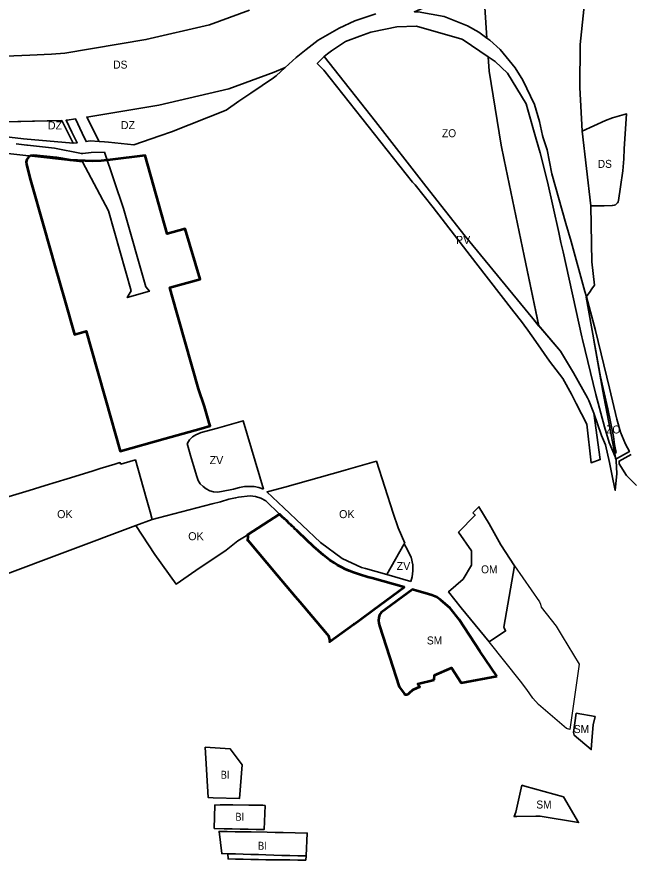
# Model space of a CAD drawing. Extents: x -650276 to -642489, y -1074311 to -1066720.
# Drawn here: x -648741 to -647822, y -1070372 to -1069108 of the extents above; entities that cross this region are included whole.
import ezdxf

# ---------------------------------------------------------------- set-up
doc = ezdxf.new("R2010")
doc.units = 0
doc.header["$LTSCALE"] = 4.8
for name, color, linetype, lineweight in [('12', 7, 'Continuous', 35), ('13', 7, 'Continuous', 35), ('15', 7, 'Continuous', 35), ('18', 7, 'Continuous', 35), ('2', 7, 'Continuous', 35), ('24', 7, 'Continuous', 35), ('25', 7, 'Continuous', 35), ('40', 7, 'Continuous', 35), ('42', 7, 'Continuous', 35), ('60', 7, 'Continuous', 53), ('61', 7, 'Continuous', 25)]:
    doc.layers.add(name, color=color, linetype=linetype, lineweight=lineweight)
doc.layers.add('62', color=7, linetype='Continuous')

msp = doc.modelspace()

# ---------------------------------------------------------------- linework, layer by layer
at = {"layer": '12'}
msp.add_lwpolyline([(-648057.11, -1069851.12), (-648053.61, -1069854.64), (-648078.54, -1069880.01), (-648059.32, -1069908.27), (-648059.5, -1069929.52), (-648071.58, -1069950.39), (-648093.67, -1069969.42), (-648074.96, -1069993.46), (-648032.85, -1070044.73), (-648008.18, -1070028.25), (-648010.44, -1070023.66), (-648010.94, -1070022.65), (-647994.71, -1069930.53), (-648015.11, -1069898.98), (-648032.94, -1069867.46), (-648048.08, -1069841.95)], close=True, dxfattribs=at)
at = {"layer": '13'}
msp.add_lwpolyline([(-648767.83, -1069946.87), (-648562.242, -1069870.301), (-648537.86, -1069861.22), (-648541.06, -1069849.78), (-648546.97, -1069828.68), (-648562.87, -1069771.85), (-648579.63, -1069776.66), (-648584.65, -1069778.1), (-648586.09, -1069775.75), (-648593.59, -1069778.06), (-648615.88, -1069784.93), (-648627.99, -1069788.67), (-648665.05, -1069799.99), (-648698.31, -1069810.16), (-648722.24, -1069817.54), (-648772.48, -1069832.83)], dxfattribs=at)
for points in [[(-648159.1, -1069896.39), (-648169.15, -1069873.81), (-648176.78, -1069851.74), (-648201.83, -1069773.86), (-648247.27, -1069786.64), (-648251.94, -1069787.95), (-648339.05, -1069812.45), (-648363.68, -1069819.31), (-648365.81, -1069819.9), (-648340.38, -1069843.78), (-648285.62, -1069895.71), (-648253.13, -1069919.7), (-648223.99, -1069932.96), (-648218.245, -1069934.595), (-648186.268, -1069943.697), (-648160.04, -1069897.73)], [(-648470.79, -1069843.51), (-648528.11, -1069858.73), (-648537.86, -1069861.22), (-648562.242, -1069870.301), (-648533.79, -1069913.49), (-648502.048, -1069957.969), (-648472.6, -1069937.81), (-648426.82, -1069906.88), (-648409.44, -1069893.25), (-648396.87, -1069885.43), (-648395.03, -1069884.22), (-648347.06, -1069853), (-648367.64, -1069833.35), (-648374.89, -1069829.22), (-648382.8, -1069826.55), (-648391.08, -1069825.45), (-648408.45, -1069827.83), (-648412.74, -1069828.72), (-648422.75, -1069830.78), (-648435.53, -1069834.44), (-648447.98, -1069837.44)]]:
    msp.add_lwpolyline(points, close=True, dxfattribs=at)
at = {"layer": '15'}
for points in [[(-648147.81, -1069355.26), (-648143.81, -1069359.39), (-648116.93, -1069393.25), (-648052.62, -1069476.32), (-647995.61, -1069549.95), (-647984.36, -1069564.49), (-647980.21, -1069569.97), (-647974.74, -1069577.39), (-647962.93, -1069594.39), (-647942.48, -1069623.82), (-647922.32, -1069649.56), (-647909.25, -1069673.35), (-647902.18, -1069687.23), (-647886.43, -1069718.16), (-647879.96, -1069776.1), (-647866.4, -1069771.43), (-647866.4, -1069771.43), (-647875.82, -1069701.85), (-647883.51, -1069682.71), (-647885.665, -1069678.788), (-647906.16, -1069641.48), (-647925.99, -1069608.57), (-647967.53, -1069559.94), (-648068.71, -1069436.57), (-648127.77, -1069361.38), (-648203.01, -1069264.73), (-648280.1, -1069166.97), (-648290.39, -1069177.69), (-648280.46, -1069187.61), (-648147.81, -1069355.26)], [(-648307.13, -1070365.57), (-648319.33, -1070365.32), (-648331.32, -1070364.96), (-648343.31, -1070364.61), (-648355.27, -1070364.25), (-648367.26, -1070363.9), (-648378.49, -1070363.57), (-648389.95, -1070363.23), (-648401.36, -1070362.89), (-648412.88, -1070362.55), (-648424.31, -1070362.21), (-648424.05, -1070370), (-648412.75, -1070370.28), (-648401.35, -1070370.5), (-648390.06, -1070370.72), (-648378.73, -1070370.94), (-648367.67, -1070371.16), (-648355.67, -1070371.28), (-648343.67, -1070371.41), (-648331.67, -1070371.53), (-648319.67, -1070371.65), (-648307.67, -1070371.78)]]:
    msp.add_lwpolyline(points, close=True, dxfattribs=at)
msp.add_lwpolyline([(-648929.112, -1069293.123), (-648642.241, -1069324.949), (-648603.386, -1069398.357), (-648569.22, -1069518.4), (-648575.15, -1069528.35), (-648541.88, -1069518.95), (-648547.3, -1069512.136), (-648581.051, -1069394.771), (-648609.304, -1069310.668), (-648629.16, -1069310.91), (-648641.98, -1069312.45), (-648643.83, -1069312.66), (-648684.39, -1069304.67), (-648724.82, -1069299.92), (-648725.82, -1069299.81), (-648741.58, -1069298.16)], dxfattribs=at)
at = {"layer": '18'}
for points in [[(-648182.01, -1070067.11), (-648197.23, -1070020.37), (-648198.22, -1070016.4), (-648198.48, -1070012.3), (-648198.17, -1070008.05), (-648197.19, -1070003.94), (-648194.84, -1070000.49), (-648147.46, -1069966.19)], [(-648147.46, -1069966.19), (-648140.96, -1069968.01), (-648128.48, -1069971.7)], [(-648128.48, -1069971.7), (-648118.75, -1069974.53), (-648111.44, -1069977.32)], [(-648111.44, -1069977.32), (-648105.79, -1069981.56), (-648091.06, -1069994.07), (-648077.68, -1070011.06), (-648046.83, -1070058.62), (-648021.35, -1070096.14), (-648074.76, -1070106.17)], [(-648152.35, -1070121.05), (-648153.85, -1070122.38), (-648156.07, -1070123.54), (-648159.02, -1070123.71), (-648159.89, -1070122.49), (-648167.48, -1070111.75), (-648182.01, -1070067.11)], [(-648074.76, -1070106.17), (-648089.22, -1070083.27), (-648114.7, -1070094.68), (-648115.11, -1070101.26), (-648139.91, -1070107.48), (-648136.61, -1070111.97)], [(-648136.61, -1070111.97), (-648139.45, -1070112.79), (-648147.02, -1070116.35), (-648152.35, -1070121.05)]]:
    msp.add_lwpolyline(points, dxfattribs=at)
for points in [[(-647902.17, -1070151.64), (-647906.6, -1070180.65), (-647905.17, -1070184.5), (-647879.81, -1070206.08), (-647878.18, -1070186.33), (-647876.74, -1070168.88), (-647873.97, -1070156.58)], [(-647962.82, -1070305.9), (-647956.36, -1070305.77), (-647898.82, -1070315.51), (-647921.51, -1070276.76), (-647979.24, -1070260.71), (-647983.6, -1070259.5), (-647992.71, -1070300.01), (-647995.46, -1070306.55), (-647991.12, -1070306.46)]]:
    msp.add_lwpolyline(points, close=True, dxfattribs=at)
at = {"layer": '2'}
msp.add_lwpolyline([(-648458.28, -1070202.26), (-648454.038, -1070277.767), (-648446.18, -1070278.15), (-648406.8, -1070279.32), (-648403.04, -1070229.15), (-648420.7, -1070204.96)], close=True, dxfattribs=at)
for points in [[(-648368.25, -1070289.71), (-648372.1, -1070289.59), (-648380.97, -1070289.44), (-648392.94, -1070289.25), (-648416.93, -1070288.85), (-648420.39, -1070288.79), (-648428.98, -1070288.92), (-648435.93, -1070288.95), (-648444.15, -1070289.16), (-648444.85, -1070324.47)], [(-648444.85, -1070324.47), (-648444.85, -1070324.47), (-648430.02, -1070324.76), (-648418.1, -1070325), (-648406.09, -1070325.23), (-648394.08, -1070325.47), (-648382.06, -1070325.7), (-648370.07, -1070325.94), (-648368.25, -1070289.71)], [(-648307.13, -1070365.57), (-648305.47, -1070331.23), (-648341.46, -1070330.48), (-648353.32, -1070330.23), (-648365.35, -1070329.98), (-648389.43, -1070329.58), (-648401.41, -1070329.39), (-648413.45, -1070329.19), (-648425.43, -1070329), (-648437.65, -1070328.8), (-648433.46, -1070361.94), (-648424.31, -1070362.21), (-648412.88, -1070362.55)], [(-648412.88, -1070362.55), (-648401.36, -1070362.89), (-648389.95, -1070363.23), (-648378.49, -1070363.57), (-648367.26, -1070363.9), (-648355.27, -1070364.25), (-648343.31, -1070364.61), (-648331.32, -1070364.96), (-648319.33, -1070365.32)]]:
    msp.add_lwpolyline(points, dxfattribs=at)
at = {"layer": '24'}
for points in [[(-648392.002, -1069097.554), (-648451.865, -1069119.456), (-648547.243, -1069141.81), (-648668.959, -1069161.838), (-648688.912, -1069163.603), (-648721.315, -1069164.952), (-648781.015, -1069167.44)], [(-648918.889, -1069268.875), (-648673.267, -1069262.895), (-648656.242, -1069297.116), (-648650.06, -1069296.39), (-648650.58, -1069295.34), (-648658.18, -1069280.27), (-648666.827, -1069262.738), (-648665.007, -1069262.694), (-648665.007, -1069262.694), (-648652.716, -1069260.657), (-648642.74, -1069281.93), (-648636.85, -1069294.49), (-648630.82, -1069293.63), (-648617.434, -1069294.508), (-648635.818, -1069257.857), (-648527.693, -1069239.938), (-648423.173, -1069215.44), (-648354.978, -1069190.492), (-648338.523, -1069183.389), (-648322.14, -1069168.56), (-648306.83, -1069156.57), (-648289.25, -1069142.79), (-648257.5, -1069124.41), (-648234.22, -1069113.6), (-648202.46, -1069103.3)]]:
    msp.add_lwpolyline(points, dxfattribs=at)
msp.add_lwpolyline([(-647860.52, -1069390.72), (-647848.24, -1069390.65), (-647845.25, -1069390.07), (-647843.41, -1069389.23), (-647841.81, -1069387.99), (-647840.42, -1069386.51), (-647839.4, -1069384.73), (-647838.79, -1069382.86), (-647836.2, -1069362.68), (-647832.29, -1069338.58), (-647832.29, -1069338.58), (-647831.19, -1069320.69), (-647830.23, -1069305.38), (-647826.928, -1069253.199), (-647848.17, -1069259.21), (-647858.37, -1069263.03), (-647893.553, -1069279.017), (-647880.326, -1069390.832)], close=True, dxfattribs=at)
at = {"layer": '25'}
msp.add_line((-647862.266, -1069668.613), (-647843.449, -1069768.252), dxfattribs=at)
for points in [[(-647948.18, -1069057.276), (-648039.666, -1069069.279), (-648040.705, -1069069.548), (-648036.291, -1069139.458)], [(-647893.553, -1069279.017), (-647896.67, -1069213.573), (-647896.362, -1069149.171), (-647886.615, -1069053.052)], [(-648036.291, -1069139.458), (-648031.92, -1069142.67), (-648016.36, -1069156.54), (-647993.8, -1069184.11)], [(-648005.47, -1069192.09), (-648024.02, -1069174.7), (-648034.421, -1069167.61)], [(-648034.421, -1069167.61), (-648034.421, -1069167.61), (-648033, -1069189), (-648015, -1069300), (-648010.092, -1069322.087), (-647980.331, -1069465.915), (-647958.34, -1069570.699), (-647925.99, -1069608.57), (-647906.16, -1069641.48), (-647885.665, -1069678.788), (-647885.663, -1069678.794), (-647883.51, -1069682.71), (-647875.82, -1069701.85), (-647875.82, -1069701.85), (-647864.19, -1069735.12), (-647858.44, -1069749.43), (-647852.63, -1069775.7), (-647850.66, -1069785.74), (-647849.165, -1069793.367)], [(-648354.978, -1069190.492), (-648423.173, -1069215.44), (-648527.693, -1069239.938), (-648635.818, -1069257.857)], [(-648526.15, -1069286.21), (-648508.95, -1069280.01), (-648427.08, -1069247.75), (-648407.73, -1069233.88), (-648389.91, -1069221.86), (-648355.81, -1069198.88), (-648351.77, -1069195.88), (-648338.523, -1069183.389), (-648354.978, -1069190.492)], [(-647993.8, -1069184.11), (-647982.58, -1069202.33), (-647965.06, -1069238.95), (-647957.56, -1069264.74), (-647953.01, -1069285.73), (-647951.841, -1069289.09)], [(-647962.2, -1069290.88), (-647974.81, -1069246.86), (-647977.29, -1069238.21), (-648005.47, -1069192.09)], [(-648635.818, -1069257.857), (-648622.995, -1069283.455), (-648617.434, -1069294.508)], [(-647880.326, -1069390.832), (-647880.326, -1069390.832), (-647893.553, -1069279.017)], [(-648617.434, -1069294.508), (-648609.425, -1069295.033), (-648603.228, -1069295.53), (-648565.18, -1069299.46), (-648526.15, -1069286.21)], [(-647852.78, -1069745.71), (-647859.722, -1069722.428), (-647872.87, -1069673.56), (-647892.79, -1069591.06), (-647892.789, -1069591.06), (-647893.75, -1069587.08), (-647922.04, -1069459.71), (-647925.16, -1069445.68), (-647928.41, -1069431.03), (-647945.28, -1069355.1), (-647956.27, -1069311.58), (-647962.2, -1069290.88)], [(-647951.841, -1069289.09), (-647945.63, -1069306.95), (-647938.77, -1069343.17), (-647918.08, -1069417.43), (-647909.67, -1069444.46), (-647889.22, -1069519.32), (-647887.087, -1069527.229), (-647885.782, -1069525.389), (-647882.551, -1069520.835), (-647878.73, -1069515.45)], [(-647878.73, -1069515.45), (-647874.75, -1069509.84), (-647878.93, -1069475.09), (-647880.318, -1069391.297), (-647880.326, -1069390.832)], [(-647843.449, -1069768.252), (-647844.371, -1069761.991), (-647842.438, -1069760.647), (-647845.086, -1069748.753), (-647846.484, -1069736.663), (-647855.158, -1069695.232), (-647865.69, -1069647.32), (-647876.061, -1069592.206), (-647862.266, -1069668.613)], [(-647841.402, -1069792.351), (-647842.489, -1069773.282), (-647842.622, -1069770.956), (-647843.337, -1069769.013), (-647843.443, -1069768.293), (-647852.78, -1069745.71)], [(-647849.165, -1069793.367), (-647843.74, -1069817.63), (-647841.402, -1069792.351)]]:
    msp.add_lwpolyline(points, dxfattribs=at)
msp.add_lwpolyline([(-648730.66, -1069290.43), (-648656.242, -1069297.116), (-648673.267, -1069262.895), (-648761.189, -1069265.035), (-648918.889, -1069268.875), (-648909.86, -1069270.02), (-648861.49, -1069275.34), (-648785.92, -1069284.2), (-648730.66, -1069290.43)], close=True, dxfattribs=at)
msp.add_arc((-648354.978, -1069190.492), 0.000000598, 264.13978, 298.69712, dxfattribs=at)
at = {"layer": '40'}
for points in [[(-648371.21, -1069815.56), (-648401.288, -1069713.154), (-648439.8, -1069724.19), (-648464.45, -1069730.89), (-648472.4, -1069734.1), (-648477.39, -1069737.44), (-648481.79, -1069741.57), (-648485.14, -1069746.55), (-648485.44, -1069747.39), (-648480.267, -1069765.316), (-648476.1, -1069780.3), (-648470.97, -1069796.9), (-648468.82, -1069802.44), (-648465.67, -1069807.49), (-648461.64, -1069811.86), (-648456.88, -1069815.39), (-648451.53, -1069817.98), (-648445.8, -1069819.51), (-648439.89, -1069819.97), (-648433.97, -1069819.3), (-648415.99, -1069815.59), (-648406.84, -1069813.23), (-648399.68, -1069811.88), (-648392.45, -1069811.44), (-648385.21, -1069811.91), (-648378.1, -1069813.29)], [(-648150, -1069954), (-648148, -1069947), (-648147, -1069938), (-648147, -1069929), (-648149.67, -1069917.83), (-648157.81, -1069902.06), (-648160.04, -1069897.73), (-648186.268, -1069943.697)]]:
    msp.add_lwpolyline(points, close=True, dxfattribs=at)
at = {"layer": '42'}
for points in [[(-648100.37, -1069107.1), (-648065.16, -1069121.12), (-648048.06, -1069130.81), (-648036.291, -1069139.458), (-648040.705, -1069069.547), (-648124.327, -1069091.181), (-648144.867, -1069099.987), (-648139.27, -1069100.05), (-648100.37, -1069107.1)], [(-648015, -1069300), (-648033, -1069189), (-648034.421, -1069167.61), (-648071.9, -1069142.06), (-648073.66, -1069140.86), (-648141.92, -1069121.66), (-648171.14, -1069122.83), (-648207.77, -1069129.95), (-648209.89, -1069130.36), (-648226.51, -1069136.57), (-648248.14, -1069144.65), (-648268.87, -1069158.61), (-648270.92, -1069159.99), (-648275.19, -1069162.87), (-648280.1, -1069166.97), (-648203.01, -1069264.73), (-648127.77, -1069361.38), (-648068.71, -1069436.57), (-647967.53, -1069559.94), (-647958.214, -1069571.3), (-647980.331, -1069465.915), (-648010.092, -1069322.087)], [(-647828.61, -1069748.41), (-647835.76, -1069730.01), (-647841.26, -1069710.69), (-647852.44, -1069664.03), (-647873.43, -1069577.87), (-647887.087, -1069527.229), (-647887.649, -1069528.021), (-647865.69, -1069647.32), (-647855.158, -1069695.232), (-647846.484, -1069736.663), (-647845.086, -1069748.753), (-647842.438, -1069760.647), (-647844.371, -1069761.991), (-647843.337, -1069769.013), (-647842.798, -1069770.477), (-647840.49, -1069769.3), (-647822.54, -1069759.29)]]:
    msp.add_lwpolyline(points, close=True, dxfattribs=at)
msp.add_lwpolyline([(-647820.09, -1069763.65), (-647838, -1069773.63), (-647837.93, -1069777.45), (-647827.16, -1069795.32), (-647811.83, -1069810.39)], dxfattribs=at)
at = {"layer": '60'}
for points in [[(-648726.23, -1069329), (-648720.26, -1069352.66), (-648699.95, -1069424.34), (-648683.77, -1069480.8), (-648668.96, -1069532.87), (-648654.264, -1069583.761), (-648636.98, -1069578.86), (-648620.94, -1069635.45), (-648607.53, -1069682.78), (-648585.959, -1069758.915), (-648518.24, -1069739.91), (-648464.32, -1069724.64), (-648450.939, -1069720.921), (-648452.25, -1069716.34), (-648459.27, -1069691.81), (-648468.49, -1069665.23), (-648508.35, -1069524.48), (-648511.542, -1069513.207), (-648465.94, -1069500.68), (-648488.2, -1069425.34), (-648515.4, -1069433.05), (-648548.56, -1069315.61), (-648600.64, -1069321.87), (-648614.51, -1069323.62), (-648627.48, -1069324.05), (-648660.81, -1069322.69), (-648681.2, -1069318.86), (-648715.26, -1069315.58), (-648720.16, -1069316.01), (-648723.27, -1069318.05), (-648725.43, -1069321.26), (-648726.48, -1069324.93)], [(-648205.77, -1069996.14), (-648160.27, -1069962.63), (-648208.27, -1069949.26), (-648214.42, -1069947.46), (-648227.23, -1069943.8), (-648236.06, -1069940.52), (-648242.53, -1069937.92), (-648248.62, -1069935.54), (-648254.18, -1069932.68), (-648260.08, -1069929.44), (-648265.24, -1069926.2), (-648271.62, -1069922.1), (-648281.22, -1069914.79), (-648295.88, -1069901.64), (-648318.63, -1069879.94), (-648321, -1069877.7), (-648323.3, -1069875.52), (-648325.6, -1069873.34), (-648327.82, -1069871.23), (-648330.09, -1069869.08), (-648332.31, -1069866.98), (-648334.54, -1069864.87), (-648336.73, -1069862.79), (-648339.13, -1069860.51), (-648343.37, -1069856.49), (-648347.06, -1069853), (-648395.03, -1069884.22), (-648394.65, -1069886.59), (-648395.15, -1069892.61), (-648394.35, -1069891.95), (-648350.48, -1069944.78), (-648323.69, -1069976.45), (-648316.73, -1069984.68), (-648278.69, -1070029.47), (-648273.67, -1070035.38), (-648271.65, -1070043.3), (-648271.95, -1070044.31), (-648271.5, -1070043.98), (-648235.74, -1070018.05), (-648234.79, -1070017.36), (-648227.16, -1070011.83)]]:
    msp.add_lwpolyline(points, close=True, dxfattribs=at)
for points in [[(-648128.48, -1069971.7), (-648140.96, -1069968.01), (-648147.46, -1069966.19), (-648194.84, -1070000.49)], [(-648111.44, -1069977.32), (-648118.75, -1069974.53), (-648128.48, -1069971.7)], [(-648021.35, -1070096.14), (-648046.83, -1070058.62), (-648077.68, -1070011.06), (-648091.06, -1069994.07), (-648105.79, -1069981.56), (-648111.44, -1069977.32)], [(-648194.84, -1070000.49), (-648197.19, -1070003.94), (-648198.17, -1070008.05), (-648198.48, -1070012.3), (-648198.22, -1070016.4), (-648197.23, -1070020.37), (-648182.01, -1070067.11)], [(-648182.01, -1070067.11), (-648167.48, -1070111.75), (-648159.89, -1070122.49), (-648159.02, -1070123.71), (-648156.07, -1070123.54)], [(-648115.11, -1070101.26), (-648114.7, -1070094.68), (-648089.22, -1070083.27), (-648074.76, -1070106.17), (-648021.35, -1070096.14)], [(-648152.35, -1070121.05), (-648147.02, -1070116.35), (-648139.45, -1070112.79), (-648136.61, -1070111.97), (-648139.91, -1070107.48), (-648115.11, -1070101.26)], [(-648156.07, -1070123.54), (-648153.85, -1070122.38), (-648152.35, -1070121.05)]]:
    msp.add_lwpolyline(points, dxfattribs=at)
at = {"layer": '61'}
msp.add_lwpolyline([(-648008.18, -1070028.25), (-648010.94, -1070022.65), (-647994.71, -1069930.53), (-647957.24, -1069984.73), (-647955.65, -1069988.28), (-647955.08, -1069992.58), (-647932.43, -1070021.22), (-647923.61, -1070036.27), (-647898.15, -1070077.99), (-647911.88, -1070175.85), (-647917.1, -1070174.56), (-647959.1, -1070138.59), (-647967.22, -1070129.11), (-647976.36, -1070116.1), (-647985.64, -1070103.59), (-648032.85, -1070044.73)], close=True, dxfattribs=at)

# ---------------------------------------------------------------- texts
at = {"layer": '62'}
for s, width, p in [('DS', 0.95, (-648596.118, -1069185.225)), ('ZO', 0.95, (-648103.473, -1069288.058)), ('DS', 0.95, (-647870.044, -1069334.044)), ('ZO', 0.95, (-647857.423, -1069732.188)), ('OM', 0.95, (-648044.853, -1069941.852)), ('SM', 0.95, (-648126.077, -1070048.464)), ('SM', 0.95, (-647905.887, -1070181.298)), ('BI', 0.85, (-648435.024, -1070249.825)), ('SM', 0.95, (-647962.077, -1070294.464)), ('BI', 0.85, (-648413.024, -1070312.825)), ('BI', 0.85, (-648379.14, -1070356.31))]:
    msp.add_text(s, height=12, dxfattribs=dict(at, width=width)).set_placement(p)
for s, p in [('DZ', (-648694.171, -1069276.367)), ('DZ', (-648584.843, -1069275.949)), ('PV', (-648082.5, -1069447.958)), ('ZV', (-648451.81, -1069778.185)), ('OK', (-648680.267, -1069859.087)), ('OK', (-648257.724, -1069859.087)), ('OK', (-648483.81, -1069892.185)), ('ZV', (-648171.5, -1069936.875))]:
    msp.add_text(s, height=12, dxfattribs=at).set_placement(p)

doc.saveas('drawing.dxf')
